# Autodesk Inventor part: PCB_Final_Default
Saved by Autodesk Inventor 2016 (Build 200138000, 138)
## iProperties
Created: 2012-01
Part Number: PCB_Final_Default
Document SubType Name: Modeling
Designer: Trevor
Density: 1 g/cm^3
Material: Generic
Appearance: Blue - Wall Paint - Glossy
Author: Trevor
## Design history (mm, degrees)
feature "Base1"
node "Cortar-Extruir2"
